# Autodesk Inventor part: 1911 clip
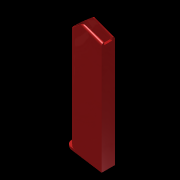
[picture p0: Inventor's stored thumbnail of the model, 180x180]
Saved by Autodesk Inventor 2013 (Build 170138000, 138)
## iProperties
Created: 2012-12
Part Number: 1911 clip
Material: Generic
Document SubType Name: Modeling
Designer: John
Density: 1 g/cm^3
Author: John
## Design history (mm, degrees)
sketch "Sketch1"
  geometry: L1 (34.849, 0)-(5.08, 4.715) reference; L2 (34.849, 115.029)-(34.849, 0); L3 (17.255, 121.432)-(34.849, 115.029); L4 (0, 7.14)-(0, 110.461); L5 (0, 110.461)-(12.289, 120.58); L6 (34.849, 0)-(-3.033, 6); L7 (-3.033, 6)-(-3.033, 7.62); L8 (0, 7.14)-(-3.033, 7.62); A1 r 5.08 centre (15.518, 116.658) between (17.255, 121.432) and (12.289, 120.58); 1 further point
  constraints: 16 end point, 2 parallel, 2 point on circle, 2 tangent, 1 centre point, 1 other
  dimensions: "d10" = 5.08 radius of A1; "d11" = 38.354 distance of L1.start L6.end
extrude "Extrusion1" new body sketch "Sketch1" distance "d13" = 13.7414; taper "d14" = 0 deg
sketch "Sketch2"
  geometry: L1 (3.033, 0)-(3.033, 13.741) reference; L2 (3.033, 13.741)-(-3.838, 13.741); L3 (3.033, 0)-(-3.838, 0); A1 r 6.871 centre (-3.838, 6.871) between (-3.838, 0) and (-3.838, 13.741); 2 further points
  constraints: 4 end point, 3 point on circle, 2 tangent, 1 centre point, 1 midpoint, 1 parallel, 1 perpendicular
extrude "Extrusion2" cut sketch "Sketch2" stored distance "d16" = 13.7414; taper "d17" = 0 deg
workplane "Work Plane1"
sketch "Sketch3"
  geometry: L1 (0, 12.289)-(0, 3.838) reference; L2 (13.741, 12.289)-(13.741, 3.838) reference; L3 (0, 3.838)-(-4.678, 3.838); L4 (-4.678, 3.838)-(-4.678, -6.416); L5 (-4.678, -6.416)-(18.163, -6.416); L6 (18.163, -6.416)-(18.163, 3.838); L7 (18.163, 3.838)-(13.741, 3.838); A1 r 6.871 centre (6.871, 7.125) between (0, 7.125) and (13.741, 7.125); 1 further point
  constraints: 10 end point, 2 parallel, 2 perpendicular, 2 point on circle, 2 point on line, 1 centre point, 1 collinear
extrude "Extrusion3" cut sketch "Sketch3" stored distance "d19" = 13.7414; taper "d20" = 0 deg
sketch "Sketch7"
  geometry: L1 (34.849, 0)-(34.849, 115.029) reference; L2 (34.849, 115.029)-(17.255, 121.432) reference; L3 (7.125, 116.328)-(7.125, 7.14) reference; L4 (34.849, 0)-(34.595, 0); L5 (34.595, 0)-(34.595, 115.121); 1 further point
  constraints: 4 end point, 2 perpendicular, 1 point on line
  dimensions: "d37" = 0.254 distance of L1.start L4.end
extrude "Extrusion6" cut sketch "Sketch7" stored distance "d38" = 25.4; taper "d39" = 0 deg
workplane "Work Plane6"
  workplane "Work Plane5"
sketch "Sketch8"
  geometry: L1 (6.871, 0)-(6.871, -17.339) reference; L2 (-6.871, 0)-(6.871, 0) reference; L3 (-6.871, 0)-(-6.871, -17.339) reference; L4 (-6.871, -17.339)-(-6.871, -22.306) reference; L5 (-6.871, -22.306)-(-6.871, -27.47) reference; L6 (6.871, -22.306)-(6.871, -27.47) reference; L7 (6.871, -17.339)-(6.871, -22.306) reference; L8 (5.728, -1.143)-(5.728, -17.339); L9 (5.728, -17.339)-(5.728, -22.306); L10 (5.728, -22.306)-(5.728, -27.47); L11 (-5.728, -27.47)-(-5.728, -22.306); L12 (-5.728, -22.306)-(-5.728, -17.339); L13 (-5.728, -17.339)-(-5.728, -1.143); L14 (-5.728, -1.143)-(5.728, -1.143); A1 r 6.871 centre (0, -27.47) between (-6.871, -27.47) and (6.871, -27.47) reference; A2 r 5.728 centre (0, -27.47) between (-5.728, -27.47) and (5.728, -27.47); 1 further point
  constraints: 14 end point, 2 point on circle, 1 centre point, 7 other
  dimensions: "d42" = 1.143 distance between parallel lines of L2 L14
extrude "Extrusion7" cut sketch "Sketch8" distance "d43" = 141.2875; taper "d44" = 0 deg
sketch "Sketch9"
  geometry: L1 (-3.838, 7.14)-(-7.125, 7.14) reference; L2 (-0.254, 110.67)-(-0.254, 7.14) reference; L3 (-0.254, 7.14)-(-0.254, 83.086); L4 (-2.226, 83.086)-(-9.707, 83.086); L5 (-9.707, 83.086)-(-9.707, 79.784); L6 (-9.707, 79.784)-(-2.226, 79.784); L7 (-2.226, 79.784)-(-2.226, 83.086); 1 further point
  constraints: 10 end point, 4 perpendicular, 1 parallel, 1 point on line
  dimensions: "d46" = 3.302 distance of L4.end L5.end
extrude "Extrusion8" cut sketch "Sketch9" distance "d47" = 7.9375; taper "d48" = 0 deg
sketch "Sketch11"
  geometry: L1 (0, 108.366)-(16.196, 114.261) reference; L2 (0, 108.366)-(0, 0) reference; L3 (21.163, 113.409)-(26.327, 109.157) reference; L4 (0, 105.813)-(21.989, 112.729); A1 r 5.08 centre (17.934, 109.487) between (21.163, 113.409) and (16.196, 114.261) reference; 1 further point
  constraints: 2 end point, 2 point on line
extrude "Extrusion10" join sketch "Sketch11" stored distance "d56" = 25.4; taper "d57" = 0 deg
sketch "Sketch10"
  geometry: L1 (2.87, 112.243)-(10.871, 112.243) reference; L2 (1.537, 121.698)-(2.87, 112.243); L3 (2.479, 115.014)-(11.262, 115.014); L4 (12.205, 121.698)-(10.871, 112.243); L5 (0, 121.698)-(13.741, 121.698) reference; L6 (6.871, 121.698)-(1.537, 121.698); L7 (6.871, 121.698)-(12.205, 121.698); 1 further point
  constraints: 12 end point, 4 point on line, 2 collinear, 1 horizontal, 1 midpoint
  dimensions: "d73" = 5.334 distance of L6.start L2.start; "d75" = 5.334 distance of L6.start L4.start
extrude "Extrusion11" cut sketch "Sketch10" distance "d58" = 25.4; taper "d59" = 0 deg
workplane "Work Plane7"
sketch "Sketch12"
  geometry: L1 (-4.001, -2.667)-(-4.401, 0) reference; L2 (-6.871, 0)-(-4.401, 0) reference; L3 (-6.871, -108.141)-(-6.871, 0) reference; L4 (6.871, -108.141)-(-6.871, -108.141) reference; L5 (6.871, 0)-(6.871, -108.141) reference; L6 (4.401, 0)-(6.871, 0) reference; L7 (4.401, 0)-(4.001, -2.667) reference; L8 (4.001, -2.667)-(-4.001, -2.667) reference; L9 (-6.871, 0)-(-6.871, -2.47); L10 (-6.871, 0)-(-4.401, 0); L11 (-6.871, -2.47)-(-7.968, -2.47); L12 (-7.968, -2.47)-(-7.968, 0.508); L13 (-7.968, 0.508)-(-4.401, 0.626); L14 (-4.401, 0.626)-(-4.401, 0); A1 r 2.47 centre (-4.401, -2.47) between (-4.401, 0) and (-6.871, -2.47); 1 further point
  constraints: 12 end point, 2 parallel, 2 point on circle, 2 tangent, 1 centre point, 1 collinear, 1 perpendicular
extrude "Extrusion12" cut sketch "Sketch12" stored distance "d61" = 152.4; taper "d62" = 0 deg
sketch "Sketch13"
  geometry: L1 (-6.871, -108.141)-(-6.871, -2.47) reference; L2 (6.871, -108.141)-(-6.871, -108.141) reference; L3 (6.871, 0)-(6.871, -108.141) reference; L4 (4.401, 0)-(6.871, 0) reference; L5 (4.401, 0)-(4.001, -2.667) reference; L6 (4.001, -2.667)-(-4.001, -2.667) reference; L7 (-4.001, -2.667)-(-4.401, 0) reference; L8 (-5.728, -3.421)-(-5.728, -8.261) reference; L9 (-5.728, -2.47)-(-5.728, -3.805); L10 (-5.728, -3.805)-(-2.82, -3.805); L11 (-2.82, -3.805)-(-2.82, -2.117); L12 (-2.82, -2.117)-(-3.122, -2.117); A1 r 2.47 centre (-4.401, -2.47) between (-4.401, 0) and (-6.871, -2.47) reference; A2 r 1.327 centre (-4.401, -2.47) between (-3.122, -2.117) and (-5.728, -2.47); 1 further point
  constraints: 8 end point, 2 perpendicular, 2 point on circle, 1 centre point, 1 coincident, 1 parallel, 1 point on line, 1 tangent
  dimensions: "d63" = 1.143 radial gap between concentric circles of A2 A1
extrude "Extrusion13" cut sketch "Sketch13" distance "d64" = 25.4; taper "d65" = 0 deg
workplane "Work Plane8"
mirror "Mirror1"
sketch "Sketch14"
  geometry: L1 (26.327, 104.81)-(26.327, 0) reference; L2 (26.327, 104.81)-(26.327, 107.479); L3 (26.327, 107.479)-(27.299, 107.479); L4 (27.299, 107.479)-(27.299, 104.423); L5 (27.299, 104.423)-(26.327, 104.423); 1 further point
  constraints: 8 end point, 2 parallel, 1 collinear, 1 perpendicular, 1 point on line
extrude "Extrusion14" join sketch "Sketch14" stored distance "d66" = 25.4; taper "d67" = 0 deg
sketch "Sketch15"
  geometry: L1 (8.669, 0)-(8.335, -2.368) reference; L2 (8.669, 0)-(0, 0) reference; L3 (0.334, -2.368)-(0, 0) reference; L4 (8.335, -2.368)-(0.334, -2.368) reference; 1 further point
extrude "Extrusion15" cut sketch "Sketch15" distance "d68" = 25.4; taper "d69" = 0 deg
sketch "Sketch17"
  geometry: L1 (1.727, 105.112)-(1.441, 107.144) reference; L2 (0.002, 105.813)-(0, 105.813) reference; L3 (0, 105.813)-(0, 0) reference; L4 (11.455, 105.813)-(11.455, 0) reference; L5 (11.455, 105.813)-(11.454, 105.813) reference; L6 (10.015, 107.144)-(9.728, 105.112) reference; L7 (9.728, 105.112)-(1.727, 105.112) reference; L8 (0, 104.161)-(11.455, 104.161); 3 further points; 2 other entities
  constraints: 2 end point, 2 point on line, 1 parallel, 2 other
sketch "Sketch18"
  geometry: L1 (0, 2.053)-(-1.22, 2.505); 1 further point
  constraints: 2 end point
sweep "Sweep1" sketch "Sketch17", "Sketch18" dims "d76" = 2 deg
sketch "Sketch19"
  geometry: L1 (11.271, 115.081)-(10.871, 112.243) reference; L2 (10.871, 112.243)-(2.87, 112.243) reference; L3 (2.87, 112.243)-(2.47, 115.081) reference; L4 (13.741, 112.452)-(13.741, 0) reference; L5 (2.47, 115.081)-(2.164, 117.25); L6 (11.271, 115.081)-(11.577, 117.25); L7 (11.577, 117.25)-(2.164, 117.25); 1 further point
  constraints: 6 end point, 2 collinear, 1 perpendicular
extrude "Extrusion17" cut sketch "Sketch19" distance "d77" = 25.4; taper "d78" = 0 deg
body "Solid1"
node "Projected Loop4"
node "Projected Loop5"
other parameters: "d18" = 9 deg, "d40" = -270 deg, "d41" = -33.3375, "d60" = 90 deg
